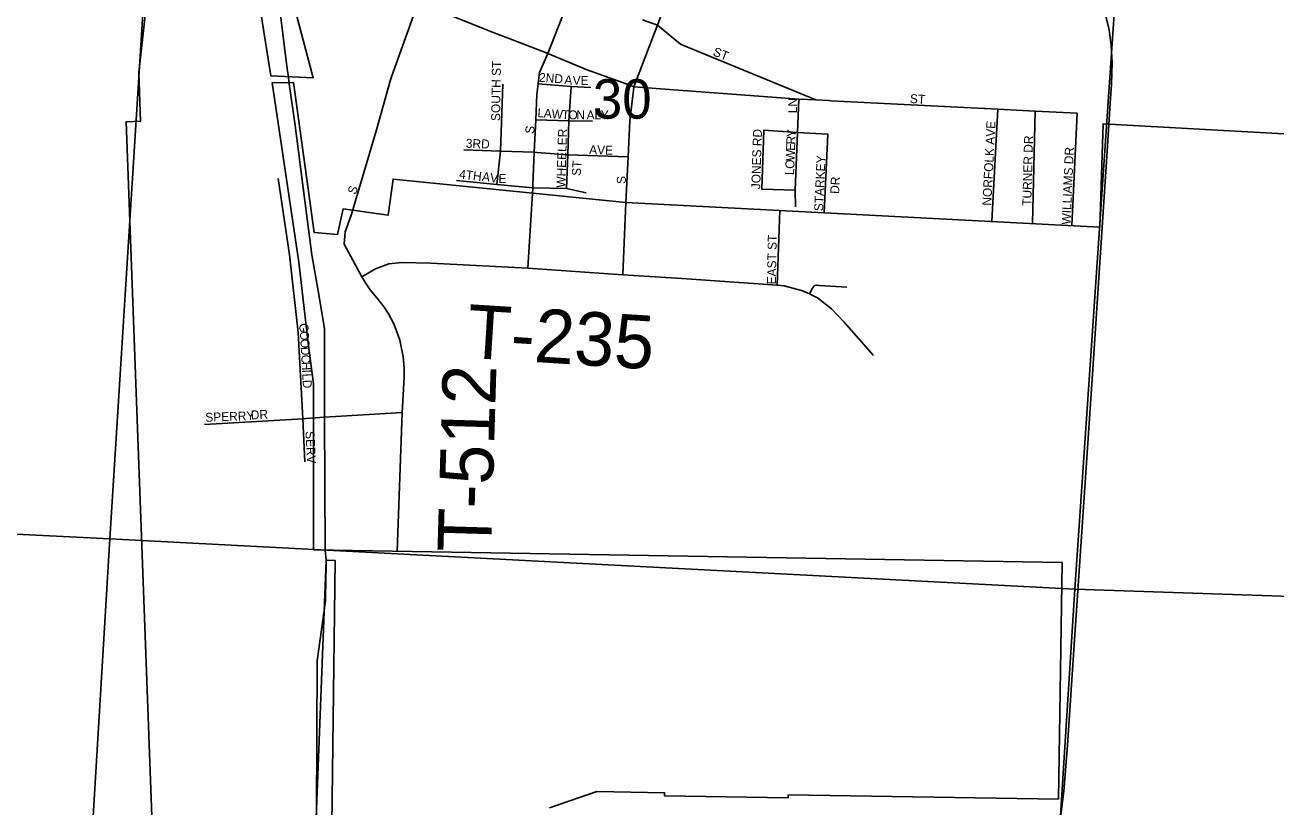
# Model space of a CAD drawing. Extents: x 1643459 to 2064572, y 425441 to 780708.
# Drawn here: x 1839127 to 1846132, y 574746 to 579125 of the extents above; entities that cross this region are included whole.
import ezdxf

# ---------------------------------------------------------------- set-up
doc = ezdxf.new("R2010")
doc.units = 0
for name, color, linetype in [('GM_X_Adjacent_County', 7, 'Continuous'), ('GM_X_Airport_Class_2', 7, 'Continuous'), ('GM_X_Airport_Class_3', 7, 'Continuous'), ('GM_X_County', 7, 'Continuous'), ('GM_X_Major_River', 7, 'Continuous'), ('GM_X_Major_River_Text', 7, 'Continuous'), ('GM_X_Minor_Lake', 7, 'Continuous'), ('GM_X_Rail_Line_Text', 7, 'Continuous'), ('GM_X_State_Route', 7, 'Continuous'), ('GM_X_Township', 7, 'Continuous'), ('GM_X_Township_Road', 7, 'Continuous'), ('RD_X_Wall', 7, 'Continuous')]:
    doc.layers.add(name, color=color, linetype=linetype)

msp = doc.modelspace()

# ---------------------------------------------------------------- linework, layer by layer
at = {"layer": 'GM_X_Airport_Class_2'}
for points in [[(1841174.5, 578817.5), (1841179.6, 578835.6), (1841328.3, 579252.1), (1841368.4, 579377.4), (1841432.7, 579578.5), (1841587.1, 579969.8), (1841727.7, 580326.4), (1841807.1, 580527.6), (1841898.6, 580759.7), (1841926.3, 580830.1), (1842100.9, 581299.2), (1842297.2, 581776.6), (1842483.5, 582242.9), (1842624.4, 582600), (1842782.2, 583008.4), (1842924.7, 583366.4), (1843082.5, 583766.7)], [(1842000.9, 578799.1), (1842008.1, 578859), (1842054.8, 578965.4), (1842187.1, 579305.5), (1842333.8, 579671.4), (1842559.5, 580234.3), (1842659, 580482.4), (1842660.9, 580487.2)], [(1842661.3, 579105), (1842668.6, 579124), (1842801.4, 579484.6), (1842857.3, 579624.8), (1842865.9, 579646.3)], [(1841328.3, 579252.1), (1841744.5, 579086), (1842041.8, 578970.5)], [(1842585.5, 579153.9), (1842668.6, 579124), (1842798.4, 579018)], [(1842533.6, 578760.2), (1842535.8, 578779.8), (1842661.3, 579105)], [(1842798.4, 579018), (1842800.7, 579016.1), (1843555.5, 578705.9)], [(1842041.8, 578970.5), (1842054.8, 578965.4), (1842278.3, 578873.2)], [(1842278.3, 578873.2), (1842294.6, 578866.5), (1842518.6, 578786)], [(1840952, 578054.4), (1840958.1, 578070.7), (1841095.4, 578538.1), (1841174.5, 578817.5)], [(1841769.5, 578232.5), (1841790.5, 578418), (1841802.5, 578793.5)], [(1841970.4, 578229.8), (1841977.5, 578412.6), (1841988.2, 578595), (1841993.8, 578736.4), (1842000.6, 578796.1), (1842000.9, 578799.1)], [(1842000.6, 578796.1), (1842184.9, 578781.1), (1842294.6, 578775.7)], [(1842159.1, 578209.3), (1842167.2, 578399), (1842172.7, 578588.7), (1842184.9, 578781.1)], [(1842518.6, 578786), (1842535.8, 578779.8), (1843460.2, 578710.8), (1843555.5, 578705.9), (1843628.3, 578702.2), (1843639.7, 578701.6)], [(1842490.5, 578130.6), (1842504.6, 578386.8), (1842514.1, 578588.7), (1842533.6, 578760.2)], [(1843441.8, 578107.1), (1843439.1, 578200), (1843452.5, 578523.2), (1843460.2, 578710.8)], [(1843639.7, 578701.6), (1844573.5, 578653.7), (1844784, 578642.9), (1845018.6, 578630.9)], [(1844540.4, 578024.6), (1844573.5, 578653.7)], [(1844767.5, 578013), (1844784, 578642.9)], [(1841988.2, 578595), (1842172.7, 578588.7), (1842304.1, 578586)], [(1844988.3, 578001.7), (1845018.6, 578630.9)], [(1843439.1, 578200), (1843253.4, 578205.7), (1843263.9, 578536.8), (1843452.5, 578523.2)], [(1843602.5, 578073.3), (1843622.5, 578513.8), (1843452.5, 578523.2)], [(1841584.6, 578426.1), (1841789.1, 578418)], [(1841789.1, 578418), (1841790.5, 578418), (1841977.5, 578412.6), (1841993.6, 578411.4)], [(1841993.6, 578411.4), (1842167.2, 578399), (1842504.6, 578386.8)], [(1840693.2, 576678.5), (1840682.5, 576920.3), (1840657.6, 577404.1), (1840607.8, 577838), (1840543.8, 578264.8)], [(1841543.9, 578253.7), (1841769.5, 578232.5), (1841969.8, 578213.7), (1842159.1, 578209.3), (1842269.1, 578185.6)], [(1840131.7, 576887.5), (1840682.5, 576920.3), (1840701.3, 576921.7)], [(1840701.3, 576921.7), (1840804.8, 576929.2)]]:
    msp.add_lwpolyline(points, dxfattribs=at)
at = {"layer": 'GM_X_County'}
msp.add_lwpolyline([(1843338.7, 577669), (1843354.5, 578086)], dxfattribs=at)
at = {"layer": 'GM_X_Major_River_Text'}
for points in [[(1841943, 577764), (1841969.8, 578213.7), (1841970.4, 578229.8)], [(1842473.8, 577725.9), (1842490.5, 578130.6)], [(1841012.8, 577714.9), (1841088.8, 577760.1), (1841163.6, 577787.4), (1841237.8, 577795.2), (1841400.4, 577791.3), (1841943, 577764), (1842473.8, 577725.9)], [(1842473.8, 577725.9), (1842775.3, 577708.4), (1842779.2, 577708.1)], [(1842779.2, 577708.1), (1843338.7, 577669), (1843378.4, 577664.7), (1843475, 577638.3), (1843520.3, 577619.6), (1843564.1, 577596.5), (1843643.5, 577535.3), (1843713.2, 577461.8), (1843877.5, 577274.5)], [(1843520.3, 577619.6), (1843536.2, 577652.3), (1843548, 577665.7), (1843557.9, 577667.6), (1843575.9, 577667.1), (1843729.4, 577656.6)], [(1841210.7, 576178.2), (1841239.6, 576954.9)]]:
    msp.add_lwpolyline(points, dxfattribs=at)
at = {"layer": 'GM_X_Minor_Lake'}
for points in [[(1841239.6, 576954.9), (1841244.6, 577054.4), (1841249.6, 577153.9), (1841250.1, 577204.8), (1841245.2, 577266.8), (1841225.8, 577359.8), (1841208.1, 577412.7), (1841189.7, 577455.6), (1841162.3, 577506.9), (1841137.7, 577545.2), (1841105, 577588.3), (1841059.6, 577642.9), (1841033.5, 577681.4), (1841012.8, 577714.9), (1840913.4, 577898.3), (1840919.2, 577967.6), (1840952, 578054.4)], [(1840804.8, 576929.2), (1841239.6, 576954.9)]]:
    msp.add_lwpolyline(points, dxfattribs=at)
at = {"layer": 'GM_X_Rail_Line_Text'}
for points in [[(1839871.3, 573785.7), (1839694.5, 578583.6), (1839774.5, 578586.5), (1839764.4, 578860.3), (1839810.1, 579262.8), (1840033.5, 579270.8), (1840084, 579366), (1840444.1, 579218.3), (1840503.9, 578841.4), (1840741.5, 578829.6), (1840529.8, 579626.8), (1840486.7, 579896.2), (1840414.9, 580812.1), (1840440.1, 581094.8), (1840575, 581480.5), (1840665, 581806.6), (1841266.6, 584100.1), (1841447.1, 584195.1), (1841794.2, 584731.1), (1841983.4, 586786.3)], [(1850624.6, 578269.9), (1845163.9, 578572.2), (1845146.1, 577993.7), (1842490.5, 578130.6), (1841188.6, 578262.1), (1841161.4, 578061.2), (1840908.4, 578095.1), (1840877.1, 577952.8), (1840746.7, 577963.1), (1840630.6, 578803.8), (1840511.2, 578802.4), (1840661.1, 577796.7), (1840712.5, 577343), (1840742.4, 577116.2), (1840742.7, 576186.1), (1844934.5, 576114.8), (1844913.8, 574790), (1843401, 574813.7), (1843400.7, 574797.7), (1842707.8, 574808.5), (1842708, 574825.5), (1842329.1, 574831.6), (1842064.5, 574740)], [(1840840, 574202), (1840863.6, 576126.7), (1840813.7, 576127.3), (1840738.7, 574203)]]:
    msp.add_lwpolyline(points, dxfattribs=at)
at = {"layer": 'GM_X_State_Route'}
for points in [[(1837916.9, 581697.5), (1839938.5, 581595.9), (1839602.8, 576247.3), (1837091.4, 576373.3)], [(1837091.4, 576373.3), (1839602.8, 576247.3), (1839292, 571084.7)]]:
    msp.add_lwpolyline(points, dxfattribs=at)
for points in [[(1845371.3, 581315.8), (1845005.6, 575965.4), (1839602.8, 576247.3), (1839938.5, 581595.9)], [(1850782.1, 581005.8), (1850462.9, 575781.2), (1845005.6, 575965.4), (1845371.3, 581315.8)], [(1839602.8, 576247.3), (1845005.6, 575965.4), (1844676.6, 570772.8), (1844270.7, 570794.7), (1839292, 571084.7)], [(1845005.6, 575965.4), (1850462.9, 575781.2), (1850117.3, 570448.6), (1849865.3, 570457.8), (1844676.6, 570772.8)]]:
    msp.add_lwpolyline(points, close=True, dxfattribs=at)
at = {"layer": 'GM_X_Township_Road'}
msp.add_lwpolyline([(1844917.7, 574627.6), (1844943.5, 574834), (1844963.7, 575092.7), (1845004.5, 575682.6), (1845104.7, 577169.7), (1845188.4, 578446), (1845203.8, 578688.2), (1845210, 578793.6), (1845215.3, 578915.3), (1845208.7, 579009.1), (1845197.6, 579098.5), (1845175.6, 579190.1)], dxfattribs=at)
at = {"layer": 'RD_X_Wall'}
for points in [[(1840600, 578846.4), (1840595.1, 578880.6), (1840524.4, 579455.3), (1840423.6, 580199.4), (1840363.8, 580586.1), (1840387.9, 581063.7), (1840432.6, 581315.2), (1840432.6, 581315.4)], [(1840607.1, 578796.1), (1840600, 578846.4)], [(1840706.9, 578040.5), (1840676.5, 578270.4), (1840640.2, 578563.3), (1840607.1, 578796.1)], [(1840808.7, 576186.1), (1840804.8, 576929.2), (1840803.4, 577425.4), (1840767.8, 577637), (1840733.5, 577839), (1840706.9, 578040.5)], [(1840812.8, 576083.1), (1840813.7, 576127.3), (1840808.7, 576185), (1840808.7, 576186.1)], [(1840811.7, 576031.4), (1840812.8, 576083.1)], [(1840756.1, 573866), (1840762.2, 575564.9), (1840808.9, 575900.5), (1840811.7, 576031.4)]]:
    msp.add_lwpolyline(points, dxfattribs=at)

# ---------------------------------------------------------------- texts
at = {"layer": 'GM_X_Adjacent_County'}
msp.add_text('30', height=221, rotation=0.00001, dxfattribs=at).set_placement((1842307, 578600.8))
at = {"layer": 'GM_X_Airport_Class_3'}
for s, rotation, p in [('ST', 338.2011, (1842974.9, 578956.8)), ('SOUTH ST', 89.13244, (1841787.2, 578587.4)), ('2ND', 355.76599, (1842004.1, 578807.8)), ('A', 355.14197, (1842145.6, 578794.6)), ('V', 359.4636, (1842193.6, 578790.6)), ('E', 359.99563, (1842238.1, 578790.2)), ('LN', 90, (1843450.4, 578631.3)), ('ST', 356.42537, (1844080.8, 578689)), ('L', 355.73333, (1841995.3, 578609.8)), ('A', 355.75902, (1842030.5, 578607.2)), ('W', 355.74187, (1842074.3, 578603.9)), ('T', 356.35432, (1842131.9, 578599.6)), ('O', 359.15948, (1842169.7, 578597.3)), ('N', 359.97035, (1842214.5, 578596.7)), ('A', 359.99285, (1842271.7, 578596.6)), ('L', 359.99563, (1842315.7, 578596.6)), ('Y', 359.99285, (1842350.9, 578596.6)), ('NORFOLK AVE', 87.07864, (1844537.2, 578112.5)), ('S', 82.87834, (1841976.5, 578513.6)), ('WHEELER', 88.26519, (1842152.4, 578213.5)), ('JONES RD', 88.23853, (1843243.6, 578204.7)), ('Y', 84.87878, (1843441.2, 578494.3)), ('TURNER DR', 88.52918, (1844761.6, 578112.3)), ('3RD', 357.79869, (1841594.6, 578438.2)), ('AVE', 358.02611, (1842285.4, 578403)), ('E', 87.73122, (1843438.3, 578420.2)), ('R', 87.71618, (1843439.6, 578455.4)), ('WILLIAMS DR', 87.50941, (1844981.6, 578006.9)), ('ST', 86.42535, (1842238.3, 578278.9)), ('O', 87.70414, (1843434.2, 578319.1)), ('W', 87.72385, (1843436, 578363.1)), ('STARKEY', 87.31425, (1843595.6, 578081.7)), ('4TH', 353.16136, (1841555.8, 578266.6)), ('A', 351.59786, (1841683.7, 578253.3)), ('V', 353.02871, (1841728.5, 578246.7)), ('E', 358.82616, (1841777.7, 578241)), ('L', 87.73122, (1843432.8, 578284)), ('S', 69.43797, (1840978.2, 578172.6)), ('S', 90, (1842491.2, 578235.3)), ('DR', 86.98901, (1843685, 578178.5)), ('G', 274.94514, (1840662, 577453)), ('O', 273.67451, (1840665.8, 577409.4)), ('O', 273.19318, (1840668.6, 577365.6)), ('D', 273.17135, (1840671, 577321.7)), ('C', 273.18785, (1840673.5, 577277.7)), ('H', 273.17135, (1840675.7, 577238.2)), ('I', 273.19211, (1840678.1, 577194.3)), ('L', 273.17075, (1840679.3, 577172.3)), ('D', 273.18516, (1840681.3, 577137.1)), ('SPERRY', 2.20147, (1840137.5, 576902.7)), ('DR', 3.01098, (1840392.5, 576915.8)), ('SERV', 273.17816, (1840697.2, 576849.8))]:
    msp.add_text(s, height=50, rotation=rotation, dxfattribs=at).set_placement(p)
at = {"layer": 'GM_X_Major_River'}
for s, rotation, p in [('T-235', 356.38773, (1841595.5, 577262.2)), ('T-512', 88.31518, (1841736.3, 576169.5))]:
    msp.add_text(s, height=300, rotation=rotation, dxfattribs=at).set_placement(p)
at = {"layer": 'GM_X_Township'}
msp.add_text('EAST ST', height=50, rotation=88.93563, dxfattribs=at).set_placement((1843331.6, 577672.2))

doc.saveas('drawing.dxf')
